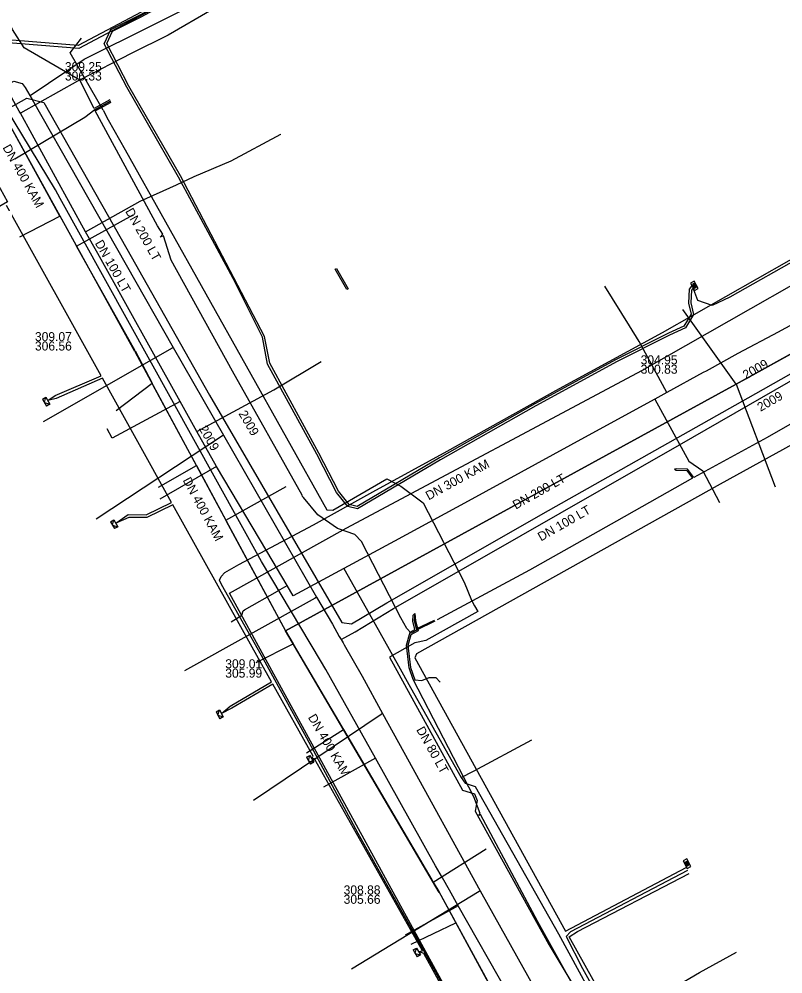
# Model space of a CAD drawing. Extents: x -600391 to -599491, y -1160176 to -1159402.
# Drawn here: x -600264.6 to -600196.8, y -1159907.9 to -1159823.2 of the extents above; entities that cross this region are included whole.
import ezdxf

# ---------------------------------------------------------------- set-up
doc = ezdxf.new("R2010")
doc.units = 0
for name, color, linetype in [('28', 7, 'Continuous'), ('31', 7, 'Continuous'), ('CETIN_linie', 7, 'Continuous'), ('Vrstva 1', 7, 'Continuous'), ('Vrstva 12', 7, 'Continuous'), ('Vrstva 13', 7, 'Continuous'), ('Vrstva 15', 7, 'Continuous'), ('Vrstva 19', 7, 'Continuous'), ('Vrstva 3', 7, 'Continuous'), ('Vrstva 42', 7, 'Continuous'), ('Vrstva 43', 7, 'Continuous'), ('Vrstva 44', 7, 'Continuous'), ('Vrstva 55', 7, 'Continuous'), ('Vrstva 58', 7, 'Continuous'), ('Vrstva 9', 7, 'Continuous')]:
    doc.layers.add(name, color=color, linetype=linetype)

# ---------------------------------------------------------------- blocks, each defined once
blk = doc.blocks.new('NN630')
at = {"layer": '31'}
for points in [[(0, -0.7), (-0.7, 0)], [(-0.7, -0.7), (-0.7, 0), (0.7, 0), (0.7, -0.7)], [(-0.7, -0.7), (0.7, -0.7)], [(0, -0.7), (0.7, 0)]]:
    blk.add_lwpolyline(points, dxfattribs=at)
blk = doc.blocks.new('NN620')
at = {"layer": '28'}
for points in [[(0.75, 0), (-0.75, 0)], [(-0.75, 0), (-0.75, -0.75)], [(0.75, -0.75), (0.75, 0)], [(-0.75, -0.75), (0.75, -0.75)], [(0.37, -0.18), (-0.38, -0.18)], [(-0.38, -0.18), (-0.38, -0.56)], [(-0.38, -0.56), (0.37, -0.56)], [(0.32, -0.23), (-0.33, -0.23)], [(-0.33, -0.23), (-0.33, -0.51)], [(-0.33, -0.51), (0.32, -0.51)], [(0.27, -0.27), (-0.28, -0.27)], [(-0.28, -0.27), (-0.28, -0.46)], [(-0.28, -0.46), (0.27, -0.46)], [(0.23, -0.32), (-0.23, -0.32)], [(-0.23, -0.32), (-0.23, -0.42)], [(-0.23, -0.42), (0.23, -0.42)], [(-0.19, -0.37), (0.19, -0.37)], [(0.23, -0.42), (0.23, -0.32)], [(0.27, -0.46), (0.27, -0.27)], [(0.32, -0.51), (0.32, -0.23)], [(0.37, -0.56), (0.37, -0.18)]]:
    blk.add_lwpolyline(points, dxfattribs=at)

msp = doc.modelspace()

# ---------------------------------------------------------------- linework, layer by layer
at = {"layer": 'CETIN_linie'}
for p, q in [((-600260.1, -1159826.21), (-600259.11, -1159824.9)), ((-600257.18, -1159831.28), (-600260.1, -1159826.21)), ((-600257.18, -1159831.28), (-600256.72, -1159832.15)), ((-600256.72, -1159832.15), (-600255.21, -1159834.8))]:
    msp.add_line(p, q, dxfattribs=at)
for points in [[(-600255.21, -1159834.8), (-600237.32, -1159866.76), (-600236.8, -1159866.78), (-600232, -1159863.99)], [(-600232, -1159863.99), (-600230.75, -1159864.66), (-600228.77, -1159866.12), (-600225.12, -1159873.15), (-600224.48, -1159874.77), (-600224.21, -1159875.25)], [(-600224.21, -1159875.25), (-600223.92, -1159875.78), (-600228.53, -1159878.34), (-600229.22, -1159878.49)], [(-600229.22, -1159878.49), (-600229.51, -1159878.56), (-600231.76, -1159879.81), (-600225.26, -1159891.62), (-600224.22, -1159891.95), (-600223.98, -1159892.52), (-600224.15, -1159893.48), (-600217.61, -1159905.3), (-600215.04, -1159909.61), (-600213.93, -1159911.53)]]:
    msp.add_lwpolyline(points, dxfattribs=at)
at = {"layer": 'Vrstva 1'}
for points in [[(-600254.35, -1159852.71), (-600266.53, -1159830.73)], [(-600163.71, -1159834.99), (-600200.98, -1159855.6)], [(-600259.536, -1159843.351), (-600254.499, -1159840.581)], [(-600264.56, -1159842.524), (-600261.015, -1159840.683)], [(-600200.98, -1159855.6), (-600205.714, -1159848.975)], [(-600254.35, -1159852.71), (-600241, -1159877.48)], [(-600256.019, -1159857.937), (-600252.837, -1159855.517)], [(-600200.98, -1159855.6), (-600241, -1159877.48)], [(-600200.98, -1159855.6), (-600197.51, -1159864.72)], [(-600252.25, -1159864.732), (-600248.899, -1159862.823)], [(-600246.29, -1159867.665), (-600240.941, -1159864.678)], [(-600227.333, -1159900.687), (-600241, -1159877.48)], [(-600243.595, -1159880.292), (-600240.315, -1159878.644)], [(-600239.137, -1159888.305), (-600235.851, -1159886.228)], [(-600227.87, -1159899.787), (-600223.17, -1159896.819)], [(-600227.38, -1159900.62), (-600213.74, -1159925.63)], [(-600229.822, -1159905.293), (-600225.878, -1159903.375)]]:
    msp.add_lwpolyline(points, dxfattribs=at)
at = {"layer": 'Vrstva 13'}
for p, q in [((-600236.21, -1159877.979), (-600236.05, -1159878.26)), ((-600236.05, -1159878.26), (-600235.729, -1159878.08)), ((-600236.05, -1159878.26), (-600235.876, -1159878.551)), ((-600235.876, -1159878.551), (-600235.77, -1159878.73))]:
    msp.add_line(p, q, dxfattribs=at)
for points in [[(-600263.68, -1159829.99), (-600263.568, -1159829.92), (-600258.86, -1159826.76), (-600246.847, -1159820.76)], [(-600268.042, -1159830.351), (-600265.11, -1159828.73), (-600264.36, -1159828.93), (-600264.11, -1159829.29), (-600263.68, -1159829.99), (-600263.477, -1159830.349), (-600250.949, -1159852.348), (-600246.504, -1159860.123), (-600238.233, -1159874.502), (-600236.83, -1159876.89), (-600236.21, -1159877.979)], [(-600373.54, -1159891.359), (-600372.925, -1159890.911), (-600370.89, -1159889.39), (-600366.85, -1159887.18), (-600352.305, -1159879.13), (-600335.078, -1159869.594), (-600317.345, -1159859.78), (-600300.082, -1159850.224), (-600283.27, -1159840.919), (-600267.84, -1159832.38), (-600263.95, -1159830.23), (-600262.43, -1159830.62), (-600255.08, -1159843.6), (-600247.73, -1159856.58), (-600236, -1159876.75), (-600235.14, -1159876.86), (-600231.99, -1159875.01), (-600217.638, -1159866.818), (-600199.226, -1159856.435), (-600175.635, -1159843.102), (-600159.56, -1159834.39), (-600159.03, -1159834.09)], [(-600235.729, -1159878.08), (-600234.8, -1159877.56), (-600231.39, -1159875.51), (-600220.063, -1159869.02), (-600206.009, -1159860.966), (-600190.21, -1159851.914), (-600186.095, -1159849.564), (-600171.436, -1159841.59), (-600171.14, -1159841.43), (-600170.949, -1159841.328), (-600160.18, -1159835.6), (-600159.206, -1159835.095), (-600158.559, -1159834.76)], [(-600250.949, -1159852.348), (-600251.049, -1159852.408), (-600262.516, -1159858.942)], [(-600246.504, -1159860.123), (-600246.591, -1159860.178), (-600257.784, -1159867.567)], [(-600238.233, -1159874.502), (-600238.348, -1159874.57), (-600249.95, -1159881.019)], [(-600235.77, -1159878.73), (-600234.17, -1159881.51), (-600232.367, -1159884.809), (-600230.48, -1159888.26), (-600223.703, -1159900.561), (-600223.01, -1159901.82), (-600218.371, -1159910.085), (-600214.068, -1159917.894), (-600213.34, -1159919.34), (-600212.9, -1159920.13), (-600213.06, -1159920.96), (-600216.681, -1159923.158)], [(-600232.367, -1159884.809), (-600232.489, -1159884.903), (-600243.816, -1159892.535)], [(-600223.703, -1159900.561), (-600223.798, -1159900.622), (-600235.121, -1159907.485)]]:
    msp.add_lwpolyline(points, dxfattribs=at)
at = {"layer": 'Vrstva 19'}
for p, q in [((-600204.238, -1159907.796), (-600200.944, -1159905.977)), ((-600206.46, -1159909.08), (-600204.238, -1159907.796))]:
    msp.add_line(p, q, dxfattribs=at)
for points in [[(-600247.517, -1159822.384), (-600251.41, -1159824.64), (-600254.69, -1159826.25), (-600259.17, -1159828.58), (-600259.44, -1159828.72), (-600264.529, -1159831.558)], [(-600261.405, -1159838.349), (-600265.07, -1159832.29), (-600265.42, -1159831.69), (-600269.464, -1159824.281)], [(-600235.81, -1159871.96), (-600240.307, -1159874.372), (-600240.846, -1159873.465), (-600242.66, -1159870.41), (-600247.12, -1159862.9), (-600248.848, -1159859.804), (-600250.336, -1159857.138), (-600257.66, -1159844.02), (-600258.737, -1159842.09), (-600261.401, -1159837.247), (-600264.529, -1159831.558), (-600264.635, -1159831.365), (-600266.076, -1159828.745), (-600266.31, -1159828.32), (-600266.915, -1159828.65)], [(-600162.36, -1159831.29), (-600162.05, -1159831.96), (-600162.73, -1159832.29), (-600166.82, -1159834.34), (-600167.21, -1159834.52), (-600171.017, -1159836.583), (-600173.707, -1159838.041), (-600186.446, -1159845.082), (-600190.06, -1159847.04), (-600194.17, -1159849.32), (-600196.99, -1159850.84), (-600197.26, -1159850.98), (-600200.83, -1159852.89), (-600203.64, -1159854.43), (-600203.9, -1159854.57), (-600207.12, -1159856.33), (-600208.202, -1159856.922), (-600214.11, -1159860.15), (-600224.77, -1159865.97), (-600231.3, -1159869.53), (-600235.81, -1159871.96)], [(-600258.737, -1159842.09), (-600253.877, -1159839.35), (-600250.657, -1159837.9), (-600249.09, -1159837.16), (-600245.817, -1159835.79), (-600241.397, -1159833.409), (-600241.394, -1159833.409)], [(-600210.69, -1159928.6), (-600211.071, -1159927.848), (-600212.567, -1159925.332), (-600213.206, -1159924.258), (-600213.809, -1159923.163), (-600213.997, -1159922.82), (-600217.918, -1159915.528), (-600221.258, -1159909.637), (-600225.65, -1159901.89), (-600226.441, -1159900.495), (-600227.057, -1159899.408), (-600227.668, -1159898.317), (-600233.004, -1159888.777), (-600237.397, -1159880.924), (-600237.874, -1159880.113), (-600243.124, -1159871.345), (-600260.994, -1159839.129), (-600261.405, -1159838.349)], [(-600207.12, -1159856.33), (-600209.6, -1159851.8), (-600210.45, -1159850.43), (-600212.63, -1159846.9)], [(-600248.848, -1159859.804), (-600242.01, -1159856.09), (-600237.812, -1159853.582)], [(-600250.336, -1159857.138), (-600256.38, -1159860.4), (-600256.83, -1159859.57)], [(-600208.202, -1159856.922), (-600205.18, -1159862.43), (-600203.94, -1159863.3), (-600202.46, -1159866.11)], [(-600247.12, -1159862.9), (-600249.62, -1159864.349), (-600252.14, -1159865.81)], [(-600235.81, -1159871.96), (-600233.039, -1159876.889), (-600230.964, -1159880.581), (-600230.959, -1159880.59), (-600229.88, -1159882.51), (-600225.4, -1159890.508), (-600225.044, -1159891.003)], [(-600245.81, -1159876.68), (-600244.86, -1159876.08), (-600244.76, -1159875.71), (-600244.62, -1159875.63), (-600241.71, -1159873.961), (-600241.663, -1159873.934), (-600240.846, -1159873.465)], [(-600225.4, -1159890.508), (-600224.3, -1159889.92), (-600219.13, -1159887.158)], [(-600233.004, -1159888.777), (-600237.607, -1159891.358)], [(-600225.044, -1159891.003), (-600224.158, -1159891.278), (-600216.76, -1159904.352), (-600212.351, -1159912.452)], [(-600225.65, -1159901.89), (-600230.358, -1159904.471)]]:
    msp.add_lwpolyline(points, dxfattribs=at)
at = {"layer": 'Vrstva 3'}
msp.add_lwpolyline([(-600236.45, -1159845.337), (-600235.433, -1159847.151), (-600235.557, -1159847.206), (-600236.574, -1159845.392)], close=True, dxfattribs=at)
at = {"layer": 'Vrstva 42'}
for points in [[(-600248.79, -1159820.17), (-600250.582, -1159821.132), (-600259.346, -1159825.816), (-600266.339, -1159825.247), (-600273.31, -1159829.476), (-600273.682, -1159830.558), (-600270.512, -1159835.778), (-600269.478, -1159836.811), (-600267.645, -1159835.87), (-600265.667, -1159839.419), (-600270.481, -1159842.194)], [(-600248.912, -1159819.992), (-600250.728, -1159820.948), (-600259.398, -1159825.561), (-600266.399, -1159824.991)], [(-600204.771, -1159847.021), (-600204.952, -1159847.256), (-600205.009, -1159848.391), (-600204.774, -1159849.406), (-600205.48, -1159850.608), (-600206.887, -1159851.24), (-600211.534, -1159853.589), (-600218.762, -1159857.517), (-600227.23, -1159862.307), (-600234.595, -1159866.667), (-600235.457, -1159866.438), (-600236.464, -1159865.215), (-600238.218, -1159861.817), (-600242.575, -1159853.814), (-600243.036, -1159851.443), (-600245.649, -1159846.226), (-600250.477, -1159837.219), (-600255.068, -1159829.248), (-600257.081, -1159825.393), (-600256.496, -1159824.126), (-600253.886, -1159822.831), (-600248.838, -1159820.082)], [(-600204.929, -1159846.899), (-600205.148, -1159847.184), (-600205.211, -1159848.409), (-600204.986, -1159849.374), (-600205.62, -1159850.452), (-600206.973, -1159851.06), (-600211.626, -1159853.411), (-600218.859, -1159857.343), (-600227.33, -1159862.133), (-600234.625, -1159866.453), (-600235.343, -1159866.262), (-600236.296, -1159865.105), (-600238.042, -1159861.723), (-600242.385, -1159853.746), (-600242.844, -1159851.377), (-600250.303, -1159837.121), (-600254.892, -1159829.152), (-600256.859, -1159825.387), (-600256.344, -1159824.274), (-600253.794, -1159823.009), (-600248.742, -1159820.258)], [(-600181.732, -1159835.603), (-600181.308, -1159836.132), (-600166.76, -1159832.161), (-600163.351, -1159838.305), (-600161.401, -1159841.771), (-600168.791, -1159845.966), (-600166.771, -1159850.319), (-600166.475, -1159851.229), (-600167.001, -1159850.385), (-600169.01, -1159846.087), (-600181.806, -1159853.142), (-600180.378, -1159855.417), (-600178, -1159857.972), (-600178.872, -1159858.58), (-600178.385, -1159857.926), (-600180.577, -1159855.57), (-600182.026, -1159853.261), (-600202.389, -1159864.484), (-600229.355, -1159879.519), (-600229.511, -1159879.87), (-600216.116, -1159904.114), (-600205.42, -1159898.474)], [(-600181.231, -1159835.327), (-600181.043, -1159835.507), (-600180.86, -1159835.88), (-600181.65, -1159836.9), (-600185.45, -1159839.02), (-600194.93, -1159844.14), (-600201.55, -1159847.87), (-600203.1, -1159848.62), (-600204.38, -1159848.18), (-600204.747, -1159847.227), (-600204.757, -1159847.072)], [(-600224.741, -1159913.329), (-600228.715, -1159906.103), (-600229.184, -1159905.923), (-600228.832, -1159905.881), (-600238.408, -1159888.831), (-600238.644, -1159888.832), (-600238.527, -1159888.61), (-600242.102, -1159882.225), (-600245.758, -1159884.352), (-600246.679, -1159884.801), (-600245.9, -1159884.154), (-600242.227, -1159882.004), (-600251.002, -1159866.313), (-600253.294, -1159867.441), (-600254.893, -1159867.416), (-600256.046, -1159867.938), (-600254.955, -1159867.165), (-600253.35, -1159867.19), (-600251.117, -1159866.091), (-600257.231, -1159855.075), (-600261.341, -1159856.864), (-600262.087, -1159857.061), (-600261.429, -1159856.612), (-600257.343, -1159854.851), (-600265.751, -1159839.756)], [(-600216.424, -1159931.321), (-600216.308, -1159930.424), (-600216.054, -1159930.101), (-600214.752, -1159929.245), (-600210.643, -1159924.902), (-600209.361, -1159923.955), (-600209.02, -1159923.095), (-600209.257, -1159918.717), (-600209.765, -1159915.778), (-600209.981, -1159915.075), (-600215.817, -1159904.626), (-600215.065, -1159904.156), (-600205.156, -1159899.006)], [(-600205.286, -1159898.735), (-600215.696, -1159904.199), (-600216.083, -1159904.585), (-600214.611, -1159907.432), (-600212.658, -1159910.968)]]:
    msp.add_lwpolyline(points, dxfattribs=at)
at = {"layer": 'Vrstva 44'}
msp.add_lwpolyline([(-600224.31, -1159913.83), (-600229.51, -1159904.42), (-600234.53, -1159895.46), (-600239.1, -1159886.99), (-600243.11, -1159879.66), (-600246.67, -1159873.36), (-600246.84, -1159872.99), (-600246.7, -1159872.66), (-600246.37, -1159872.32), (-600245.12, -1159871.59), (-600238.49, -1159868.07), (-600233.22, -1159865.15), (-600226.64, -1159861.55), (-600216.98, -1159856.16), (-600207.52, -1159851.02), (-600196.27, -1159844.63), (-600187.87, -1159840.83), (-600180.35, -1159836.34), (-600173.18, -1159832.26), (-600165.31, -1159827.98), (-600164.17, -1159827.44), (-600164.02, -1159827.18), (-600163.23, -1159825.99), (-600157.45, -1159822.77)], dxfattribs=at)
at = {"layer": 'Vrstva 55'}
for points in [[(-600256.571, -1159830.382), (-600257.984, -1159831.143), (-600259.24, -1159828.63), (-600264.18, -1159825.77), (-600265.22, -1159824.13), (-600265.28, -1159823.98)], [(-600256.515, -1159830.488), (-600257.93, -1159831.25), (-600258.8, -1159831.94), (-600265.03, -1159835.65)], [(-600227.72, -1159876.636), (-600229.403, -1159877.453), (-600229.836, -1159877.685), (-600230.23, -1159877.28), (-600230.76, -1159876.32), (-600234.23, -1159869.57), (-600234.82, -1159868.93), (-600236.36, -1159868.41), (-600238.12, -1159867.18), (-600239.4, -1159865.64), (-600239.48, -1159865.56), (-600239.502, -1159865.459), (-600245.68, -1159854.45), (-600251.15, -1159844.61), (-600251.825, -1159842.43), (-600252.13, -1159842.55), (-600251.892, -1159842.295), (-600252.35, -1159841.55), (-600257.873, -1159831.356), (-600256.458, -1159830.594)], [(-600177.26, -1159846.95), (-600177.2, -1159847.08), (-600176.71, -1159847.87), (-600176.88, -1159848.38), (-600180.27, -1159850.28), (-600188.66, -1159854.85), (-600198.23, -1159860.34), (-600204.737, -1159863.881), (-600205.289, -1159863.141), (-600206.287, -1159863.1), (-600206.46, -1159863.15), (-600206.293, -1159863.22), (-600205.351, -1159863.259), (-600204.843, -1159863.94), (-600211.6, -1159867.76), (-600219.34, -1159872.1), (-600227.51, -1159876.52)], [(-600208.068, -1159926.408), (-600208.44, -1159926.61), (-600208.644, -1159926.75), (-600209.38, -1159926.73), (-600210.16, -1159924.93), (-600211, -1159916.94), (-600218.58, -1159903.31), (-600223.67, -1159893.79), (-600223.81, -1159893.86), (-600223.699, -1159893.694), (-600224.26, -1159892.22), (-600229.65, -1159881.81), (-600230.02, -1159880.76), (-600230.26, -1159878.76), (-600229.908, -1159877.587), (-600229.5, -1159877.369), (-600229.69, -1159876.616), (-600229.659, -1159876.093), (-600229.51, -1159875.95)], [(-600229.51, -1159875.95), (-600229.449, -1159876.593), (-600229.221, -1159877.492), (-600229.856, -1159877.831), (-600230.138, -1159878.77), (-600229.902, -1159880.733), (-600229.519, -1159881.822), (-600228.87, -1159881.88), (-600228.22, -1159881.61), (-600227.65, -1159881.61), (-600227.251, -1159882.028)], [(-600229.51, -1159875.95), (-600229.541, -1159876.127), (-600229.57, -1159876.604), (-600229.39, -1159877.314), (-600227.773, -1159876.528)]]:
    msp.add_lwpolyline(points, dxfattribs=at)
at = {"layer": 'Vrstva 58'}
msp.add_lwpolyline([(-600220.159, -1159921.243), (-600245.973, -1159874.147), (-600235.595, -1159868.362), (-600209.303, -1159854.361), (-600163.546, -1159828.331), (-600142.156, -1159815.889)], dxfattribs=at)
at = {"layer": 'Vrstva 9'}
msp.add_line((-600241, -1159877.48), (-600200.98, -1159855.6), dxfattribs=at)
for points in [[(-600254.327, -1159852.654), (-600259.536, -1159843.351), (-600259.579, -1159843.274), (-600261.004, -1159840.703), (-600261.015, -1159840.683), (-600266.53, -1159830.73)], [(-600200.98, -1159855.6), (-600194.426, -1159851.976), (-600194.308, -1159851.911), (-600194.164, -1159851.831), (-600193.88, -1159851.674), (-600189.351, -1159849.169), (-600189.06, -1159849.008), (-600187.688, -1159848.25), (-600187.401, -1159848.091), (-600163.71, -1159834.99)], [(-600254.327, -1159852.654), (-600252.837, -1159855.517), (-600252.782, -1159855.619), (-600248.913, -1159862.798), (-600248.899, -1159862.823), (-600246.29, -1159867.665), (-600246.28, -1159867.683), (-600241, -1159877.48)], [(-600241, -1159877.48), (-600240.315, -1159878.644), (-600240.295, -1159878.678), (-600235.98, -1159886.009), (-600235.851, -1159886.228), (-600227.999, -1159899.568), (-600227.87, -1159899.787), (-600227.38, -1159900.62)], [(-600227.38, -1159900.62), (-600225.878, -1159903.375), (-600225.877, -1159903.377), (-600221.797, -1159910.856), (-600221.592, -1159911.232), (-600220.457, -1159913.315), (-600220.3, -1159913.602), (-600220.054, -1159914.052), (-600219.821, -1159914.48), (-600213.74, -1159925.63)]]:
    msp.add_lwpolyline(points, dxfattribs=at)

# ---------------------------------------------------------------- block references
at = {"layer": 'Vrstva 43', "xscale": 0.5, "yscale": 0.5}
for name, p, rotation in [('NN620', (-600204.85, -1159846.96), 119.99999999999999), ('NN630', (-600262.087, -1159857.061), -59.99999999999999), ('NN630', (-600256.046, -1159867.938), -59.99999999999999), ('NN630', (-600246.679, -1159884.801), -61.000000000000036), ('NN630', (-600238.644, -1159888.832), -59.99999999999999), ('NN620', (-600205.516, -1159898.23), 117.99999999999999), ('NN630', (-600229.184, -1159905.923), -59.99999999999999)]:
    msp.add_blockref(name, p, dxfattribs=dict(at, rotation=rotation))

# ---------------------------------------------------------------- texts
at = {"layer": 'Vrstva 12'}
for s, p in [('309.25', (-600260.571, -1159827.827)), ('306.33', (-600260.571, -1159828.659)), ('309.07', (-600263.231, -1159851.781)), ('306.56', (-600263.231, -1159852.613)), ('304.95', (-600209.456, -1159853.839)), ('300.83', (-600209.456, -1159854.671)), ('309.01', (-600246.333, -1159880.804)), ('305.99', (-600246.333, -1159881.636)), ('308.88', (-600235.826, -1159900.867)), ('305.66', (-600235.826, -1159901.699))]:
    msp.add_text(s, height=0.8, dxfattribs=at).set_placement(p)
for s, rotation, p in [('DN 400 KAM', 299.25586, (-600266.129, -1159834.602)), ('DN 300 KAM', 28.64789, (-600228.275, -1159865.915)), ('DN 400 KAM', 298.33912, (-600250.135, -1159864.118)), ('DN 400 KAM', 300.45907, (-600239.021, -1159885.152))]:
    msp.add_text(s, height=0.8, rotation=rotation, dxfattribs=at).set_placement(p)
at = {"layer": 'Vrstva 15'}
for s, rotation, p in [('DN 200 LT', 299.54234, (-600255.241, -1159840.256)), ('DN 100 LT', 299.65693, (-600257.937, -1159843.085)), ('2009', 29.39273, (-600200.111, -1159855.202)), ('2009', 29.7938, (-600198.822, -1159858.057)), ('2009', 300.17259, (-600245.181, -1159858.213)), ('2009', 299.77151, (-600248.698, -1159859.541)), ('DN 200 LT', 29.39273, (-600220.541, -1159866.733)), ('DN 100 LT', 29.79381, (-600218.306, -1159869.561)), ('DN 80 LT', 299.31315, (-600229.403, -1159886.251))]:
    msp.add_text(s, height=0.8, rotation=rotation, dxfattribs=at).set_placement(p)

doc.saveas('drawing.dxf')
